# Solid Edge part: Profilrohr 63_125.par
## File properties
Username: ahadarics
Dokumentum tartalom típus: 0
Author: ahadarics
Last saved by: ahadarics
Revision: 82
Sűrűség: 0,000 kg/m^3
Pontosság: 0,990
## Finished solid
Body 1: solid body, 175 faces, 519 edges, 346 vertices.
  Faces by surface: cylinder 107, plane 68
  Edges by curve: line 305, circle 214
Bounding box of the edges (mm): 70.400 x 70.400 x 179.000, from (-35.2, -35.2, -139.5) to (35.2, 35.2, 39.5).
Cylindrical faces by radius (mm): R0.1 x16, R0.2 x30, R0.5 x28, R1 x8, R3.75 x8, R4.8 x4, R6 x4, R31.5 x1, R33.8 x8
Planar faces by outward normal: +x 6, +y 6, +z 1, -x 4, -y 4, -z 1, oblique 46
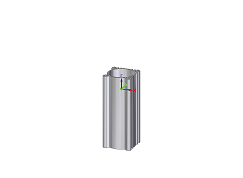
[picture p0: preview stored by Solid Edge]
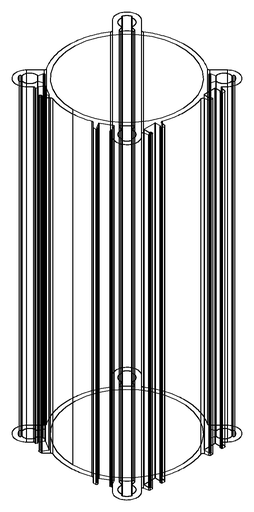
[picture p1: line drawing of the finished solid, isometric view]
